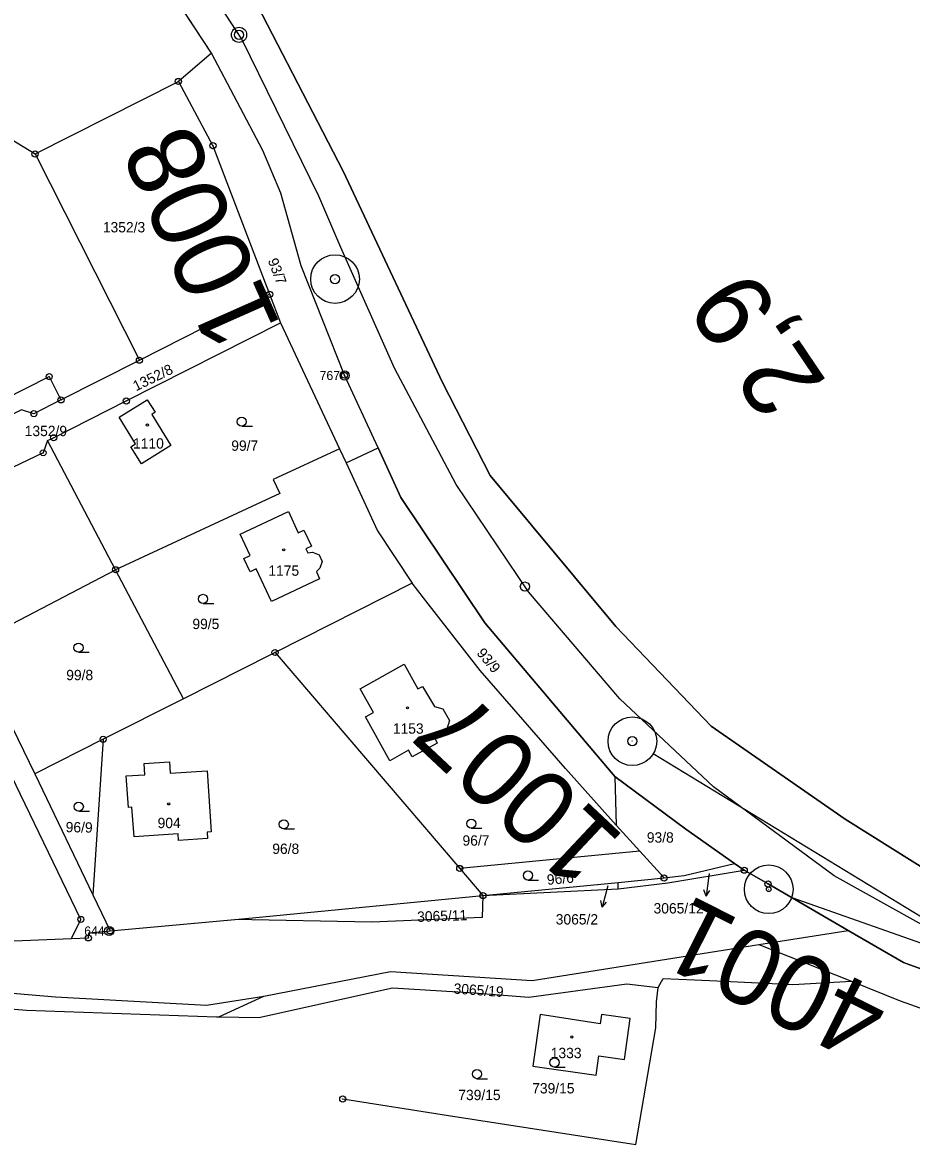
# Model space of a CAD drawing. Extents: x -728802 to -728097, y -1073200 to -1072700.
# Drawn here: x -728717.3 to -728571.2, y -1073057.7 to -1072873.2 of the extents above; entities that cross this region are included whole.
import ezdxf

# ---------------------------------------------------------------- set-up
doc = ezdxf.new("R2010")
doc.units = 0
for name, color, linetype in [('A5_JŽM', 7, 'Continuous'), ('body_ZBP', 7, 'Continuous'), ('body_ZBP-zničený', 7, 'Continuous'), ('body_ZBP_nový', 7, 'Continuous'), ('Hranice parcel', 7, 'Continuous'), ('Pop  PČ popisy', 7, 'Continuous')]:
    doc.layers.add(name, color=color, linetype=linetype)

msp = doc.modelspace()

# ---------------------------------------------------------------- linework, layer by layer
at = {"layer": 'A5_JŽM'}
msp.add_line((-728664.46, -1072931.23), (-728664.36, -1072931.23), dxfattribs=at)
for points in [[(-728320.8, -1073026.91), (-728374.01, -1073033.72), (-728429.1, -1073040.75), (-728461.93, -1073044.27), (-728481.2, -1073044.81), (-728499.35, -1073043.65), (-728506.01, -1073042.74), (-728514.57, -1073041.33), (-728535.85, -1073036), (-728561.35, -1073026.11), (-728583.96, -1073013.52), (-728603.76, -1072998.89), (-728619.19, -1072984.42), (-728634.19, -1072966.82), (-728646.08, -1072949.19), (-728656.18, -1072930.07), (-728664.99, -1072910.23), (-728668.63, -1072901.81), (-728681.25, -1072876.02), (-728691.89, -1072859.66)], [(-728541.12, -1073039.22), (-728572.55, -1073027.78), (-728581.66, -1073022.5), (-728594.83, -1073014.86), (-728598.74, -1073012.6), (-728600.31, -1073011.5), (-728608.33, -1073005.87), (-728620.02, -1072997.18), (-728641.33, -1072971.93), (-728655.13, -1072951.34), (-728658.89, -1072943.19), (-728664.41, -1072931.23), (-728671.52, -1072913.23), (-728674.84, -1072901.32), (-728677.82, -1072894.3), (-728686.27, -1072878.28), (-728697.93, -1072860.51)], [(-728681.24, -1072865.51), (-728664.64, -1072897.67), (-728648.31, -1072932.44), (-728640.48, -1072947.72), (-728619.81, -1072972.56), (-728604.14, -1072988.92), (-728582.13, -1073004.22), (-728556.03, -1073020.59)]]:
    msp.add_lwpolyline(points, dxfattribs=at)
for centre, radius in [((-728681.73, -1072875.28), 1.25), ((-728681.73, -1072875.28), 0.752), ((-728664.41, -1072931.23), 0.499), ((-728634.77, -1072965.97), 0.75)]:
    msp.add_circle(centre, radius, dxfattribs=at)
at = {"layer": 'body_ZBP'}
for p, q in [((-728665.94, -1072915.49), (-728665.98, -1072915.4)), ((-728617.07, -1072991.42), (-728617.15, -1072991.35)), ((-728524.75, -1073047.65), (-728613.69, -1072993.47)), ((-728594.73, -1073015.73), (-728594.68, -1073015.74))]:
    msp.add_line(p, q, dxfattribs=at)
msp.add_lwpolyline([(-728590.94, -1073017.06), (-728505.86, -1073047.04)], dxfattribs=at)
for centre, radius in [((-728665.96, -1072915.44), 0.756), ((-728617.11, -1072991.39), 4), ((-728617.11, -1072991.39), 0.756), ((-728594.71, -1073015.73), 0.378)]:
    msp.add_circle(centre, radius, dxfattribs=at)
at = {"layer": 'body_ZBP-zničený'}
msp.add_circle((-728665.96, -1072915.44), 4, dxfattribs=at)
at = {"layer": 'body_ZBP_nový'}
msp.add_circle((-728594.71, -1073015.73), 4, dxfattribs=at)
at = {"layer": 'Hranice parcel'}
for p, q in [((-728686.27, -1072878.28), (-728697.93, -1072860.51)), ((-728686.27, -1072878.28), (-728691.7, -1072882.94)), ((-728740.25, -1072879.56), (-728715.25, -1072894.87)), ((-728715.25, -1072894.87), (-728691.7, -1072882.94)), ((-728715.25, -1072894.87), (-728698.09, -1072928.77)), ((-728698.09, -1072928.77), (-728676.7, -1072917.94)), ((-728676.7, -1072917.94), (-728674.91, -1072922.64)), ((-728674.91, -1072922.64), (-728665.22, -1072943.32)), ((-728710.98, -1072935.3), (-728698.09, -1072928.77)), ((-728681.29, -1072939.62), (-728679.54, -1072939.62)), ((-728702.01, -1072963.21), (-728713.2, -1072941.99)), ((-728665.22, -1072943.32), (-728664.14, -1072945.63)), ((-728664.14, -1072945.63), (-728658.89, -1072943.19)), ((-728725.65, -1072975.57), (-728702.01, -1072963.21)), ((-728690.84, -1072984.4), (-728702.01, -1072963.21)), ((-728653.3, -1072965.44), (-728675.82, -1072976.81)), ((-728651.42, -1072967.85), (-728653.3, -1072965.44)), ((-728687.64, -1072968.75), (-728685.89, -1072968.75)), ((-728707.72, -1073020.69), (-728728.75, -1072977.2)), ((-728708.11, -1072976.78), (-728706.36, -1072976.78)), ((-728675.82, -1072976.81), (-728645.47, -1073012.3)), ((-728690.84, -1072984.4), (-728704.05, -1072991.07)), ((-728704.05, -1072991.07), (-728715.29, -1072996.74)), ((-728704.05, -1072991.07), (-728705.76, -1073016.63)), ((-728715.29, -1072996.74), (-728705.76, -1073016.63)), ((-728620.02, -1072997.18), (-728619.75, -1073005.17)), ((-728708.06, -1073002.9), (-728706.31, -1073002.9)), ((-728674.38, -1073005.8), (-728672.63, -1073005.8)), ((-728643.57, -1073005.69), (-728641.82, -1073005.69)), ((-728615.86, -1073009.48), (-728619.75, -1073005.17)), ((-728615.86, -1073009.48), (-728645.47, -1073012.3)), ((-728611.9, -1073013.87), (-728615.86, -1073009.48)), ((-728645.47, -1073012.3), (-728641.66, -1073016.76)), ((-728600.31, -1073011.5), (-728598.74, -1073012.6)), ((-728598.74, -1073012.6), (-728594.83, -1073014.86)), ((-728641.66, -1073016.76), (-728619.47, -1073014.61)), ((-728634.26, -1073014.22), (-728632.51, -1073014.22)), ((-728619.47, -1073014.61), (-728611.9, -1073013.87)), ((-728619.45, -1073015.63), (-728619.47, -1073014.61)), ((-728594.83, -1073014.86), (-728581.66, -1073022.5)), ((-728705.76, -1073016.63), (-728702.91, -1073022.58)), ((-728641.66, -1073016.76), (-728619.45, -1073015.63)), ((-728709.27, -1073023.84), (-728707.72, -1073020.69)), ((-728702.91, -1073022.58), (-728682.44, -1073020.7)), ((-728726.2, -1073024.5), (-728709.27, -1073023.84)), ((-728596.32, -1073024.82), (-728581.66, -1073022.5)), ((-728596.32, -1073024.82), (-728581.13, -1073030.83)), ((-728685.04, -1073036.71), (-728677.64, -1073033.29)), ((-728613.14, -1073034.24), (-728612.89, -1073031.9)), ((-728629.9, -1073044.95), (-728628.15, -1073044.95)), ((-728642.65, -1073046.86), (-728640.9, -1073046.86)), ((-728664.69, -1073050.2), (-728647.33, -1073052.89)), ((-728647.33, -1073052.89), (-728616.56, -1073057.69))]:
    msp.add_line(p, q, dxfattribs=at)
for points in [[(-728509.9, -1073046.86), (-728508.93, -1073042.5), (-728513.22, -1073039.89), (-728513.66, -1073035.13), (-728514.64, -1073029.26), (-728515.01, -1073025.35), (-728515.38, -1073021.39), (-728541.24, -1073024.99), (-728556.03, -1073020.59), (-728582.13, -1073004.22), (-728604.14, -1072988.92), (-728619.81, -1072972.56), (-728640.48, -1072947.72), (-728648.31, -1072932.44), (-728664.64, -1072897.67), (-728681.24, -1072865.51), (-728697.08, -1072846.24), (-728715.84, -1072827.08), (-728724.75, -1072819.77), (-728735.02, -1072812.66), (-728738.25, -1072810.52), (-728762.66, -1072797.6), (-728789.42, -1072788.62), (-728800, -1072785.75)], [(-728658.89, -1072943.19), (-728664.41, -1072931.23), (-728671.52, -1072913.23), (-728674.84, -1072901.32), (-728677.82, -1072894.3), (-728686.27, -1072878.28)], [(-728691.7, -1072882.94), (-728686.01, -1072893.51), (-728676.7, -1072917.94)], [(-728713.2, -1072941.99), (-728712.19, -1072941.51), (-728700.25, -1072935.47), (-728674.91, -1072922.64)], [(-728742.89, -1072957.06), (-728742.61, -1072946.49), (-728720.35, -1072935.22), (-728712.92, -1072931.46), (-728710.98, -1072935.3)], [(-728710.98, -1072935.3), (-728715.44, -1072937.56), (-728717.46, -1072936.9), (-728720.53, -1072938.46)], [(-728699.51, -1072943.01), (-728698.75, -1072942.53), (-728701.45, -1072938.15), (-728696.81, -1072935.29), (-728695.52, -1072937.32), (-728696.05, -1072937.71), (-728692.92, -1072942.8), (-728697.78, -1072945.82), (-728699.51, -1072943.01)], [(-728713.2, -1072941.99), (-728713.91, -1072943.99), (-728718.94, -1072946.39)], [(-728665.22, -1072943.32), (-728676.11, -1072948.38), (-728675.03, -1072950.69), (-728702.01, -1072963.21)], [(-728658.89, -1072943.19), (-728655.13, -1072951.34), (-728641.33, -1072971.93), (-728620.02, -1072997.18)], [(-728664.14, -1072945.63), (-728658.98, -1072956.84), (-728653.3, -1072965.44)], [(-728679.92, -1072960.89), (-728681.56, -1072957.34), (-728673.63, -1072953.66), (-728671.99, -1072957.16), (-728671.07, -1072956.72), (-728669.83, -1072959.34), (-728670.78, -1072959.75), (-728670.44, -1072960.42), (-728669.64, -1072960.34), (-728668.55, -1072960.74), (-728668.06, -1072961.84), (-728668.47, -1072962.95), (-728669.01, -1072963.48), (-728668.94, -1072963.65), (-728668.49, -1072964.73), (-728676.42, -1072968.43), (-728678.91, -1072963.06), (-728679.91, -1072963.53), (-728680.92, -1072961.35), (-728679.92, -1072960.89)], [(-728619.75, -1073005.17), (-728628.12, -1072995.9), (-728642.12, -1072979.76), (-728651.42, -1072967.85)], [(-728725.65, -1072975.57), (-728722.83, -1072981.3), (-728715.29, -1072996.74)], [(-728675.82, -1072976.81), (-728676.45, -1072977.13), (-728690.84, -1072984.4)], [(-728649.64, -1072985.67), (-728648.26, -1072986.08), (-728647.18, -1072987.97), (-728647.58, -1072989.39), (-728647.91, -1072990.21), (-728648.9, -1072990.74), (-728649.27, -1072990.62), (-728649.61, -1072990.81), (-728649.16, -1072991.69), (-728653.29, -1072993.97), (-728653.91, -1072992.88), (-728656.95, -1072994.61), (-728660.97, -1072987.38), (-728659.66, -1072986.65), (-728661.82, -1072982.76), (-728654.58, -1072978.73), (-728652.33, -1072982.79), (-728651.61, -1072982.39), (-728649.64, -1072985.67)], [(-728699.33, -1073002.26), (-728699.87, -1073002.3), (-728700.26, -1072997.11), (-728697.19, -1072996.91), (-728697.31, -1072995.08), (-728693.16, -1072994.76), (-728693.04, -1072996.64), (-728686.96, -1072996.24), (-728686.3, -1073006.28), (-728686.99, -1073006.32), (-728686.92, -1073007.41), (-728691.67, -1073007.72), (-728691.74, -1073006.63), (-728698.96, -1073007.1), (-728699.33, -1073002.26)], [(-728620.02, -1072997.18), (-728608.33, -1073005.87), (-728600.31, -1073011.5)], [(-728619.45, -1073015.63), (-728611.28, -1073014.65), (-728598.74, -1073012.6)], [(-728611.9, -1073013.87), (-728608.61, -1073013.46), (-728600.31, -1073011.5)], [(-728641.66, -1073016.76), (-728641.79, -1073020.38), (-728659.93, -1073021.15), (-728682.44, -1073020.7)], [(-728682.44, -1073020.7), (-728679.52, -1073020.43), (-728641.66, -1073016.76)], [(-728709.27, -1073023.84), (-728706.47, -1073023.73), (-728706.38, -1073022.87), (-728702.91, -1073022.58)], [(-728581.66, -1073022.5), (-728572.55, -1073027.78), (-728541.12, -1073039.22)], [(-728677.64, -1073033.29), (-728656.86, -1073029.26), (-728633.57, -1073030.7), (-728596.32, -1073024.82)], [(-728685.04, -1073036.71), (-728678.46, -1073036.79), (-728656.52, -1073031.93), (-728643.1, -1073032.77), (-728634.11, -1073033.48), (-728618.03, -1073031.25), (-728612.89, -1073031.9), (-728612.03, -1073030.4), (-728606.88, -1073030.63), (-728603.24, -1073030.8), (-728590.77, -1073031.36), (-728581.13, -1073030.83)], [(-728581.13, -1073030.83), (-728573.14, -1073034.08), (-728549.07, -1073042.59), (-728532.43, -1073048.47), (-728518.44, -1073050.34), (-728510.92, -1073051.33), (-728509.9, -1073046.86)], [(-728800, -1073042), (-728754.78, -1073034.24), (-728729.22, -1073031.95), (-728711.87, -1073033.42), (-728687.08, -1073034.79), (-728677.64, -1073033.29)], [(-728800, -1073046.03), (-728776.74, -1073043.15), (-728750.7, -1073037.52), (-728729.9, -1073034.48), (-728716.63, -1073035.6), (-728685.42, -1073036.71), (-728685.04, -1073036.71)], [(-728616.56, -1073057.69), (-728613.27, -1073038.52), (-728613.14, -1073034.24)], [(-728633.49, -1073044.79), (-728623.08, -1073046.28), (-728622.63, -1073043.11), (-728618.43, -1073043.72), (-728617.47, -1073036.95), (-728622.19, -1073036.29), (-728622.39, -1073037.83), (-728632.28, -1073036.32), (-728633.49, -1073044.79)]]:
    msp.add_lwpolyline(points, dxfattribs=at)
for centre, radius in [((-728691.7, -1072882.94), 0.5), ((-728691.7, -1072882.94), 0.0303), ((-728686.01, -1072893.51), 0.5), ((-728715.25, -1072894.87), 0.5), ((-728715.25, -1072894.87), 0.0303), ((-728686.01, -1072893.51), 0.0303), ((-728676.7, -1072917.94), 0.5), ((-728676.7, -1072917.94), 0.0303), ((-728698.09, -1072928.77), 0.5), ((-728698.09, -1072928.77), 0.0303), ((-728712.92, -1072931.46), 0.5), ((-728712.92, -1072931.46), 0.0303), ((-728664.39, -1072931.28), 0.75), ((-728664.41, -1072931.23), 0.5), ((-728664.41, -1072931.23), 0.0303), ((-728664.39, -1072931.28), 0.03), ((-728710.98, -1072935.3), 0.5), ((-728710.98, -1072935.3), 0.0303), ((-728700.25, -1072935.47), 0.5), ((-728700.25, -1072935.47), 0.0303), ((-728715.44, -1072937.56), 0.5), ((-728715.44, -1072937.56), 0.0303), ((-728696.79, -1072939.42), 0.175), ((-728681.29, -1072938.87), 0.75), ((-728712.19, -1072941.51), 0.5), ((-728712.19, -1072941.51), 0.0303), ((-728713.91, -1072943.99), 0.5), ((-728713.91, -1072943.99), 0.0303), ((-728674.39, -1072959.93), 0.175), ((-728702.01, -1072963.21), 0.5), ((-728702.01, -1072963.21), 0.0303), ((-728687.64, -1072968), 0.75), ((-728708.11, -1072976.03), 0.75), ((-728675.82, -1072976.81), 0.5), ((-728675.82, -1072976.81), 0.0303), ((-728654.05, -1072985.9), 0.175), ((-728704.05, -1072991.07), 0.5), ((-728704.05, -1072991.07), 0.0303), ((-728708.06, -1073002.15), 0.75), ((-728693.29, -1073001.7), 0.175), ((-728674.38, -1073005.05), 0.75), ((-728643.57, -1073004.94), 0.75), ((-728645.47, -1073012.3), 0.5), ((-728645.47, -1073012.3), 0.0303), ((-728634.26, -1073013.47), 0.75), ((-728598.74, -1073012.6), 0.5), ((-728598.74, -1073012.6), 0.0303), ((-728611.9, -1073013.87), 0.5), ((-728611.9, -1073013.87), 0.0303), ((-728594.83, -1073014.86), 0.5), ((-728594.83, -1073014.86), 0.0303), ((-728641.66, -1073016.76), 0.5), ((-728641.66, -1073016.76), 0.0303), ((-728707.72, -1073020.69), 0.5), ((-728707.72, -1073020.69), 0.0303), ((-728703.06, -1073022.59), 0.75), ((-728702.91, -1073022.58), 0.5), ((-728706.47, -1073023.73), 0.5), ((-728706.47, -1073023.73), 0.0303), ((-728703.06, -1073022.59), 0.03), ((-728702.91, -1073022.58), 0.0303), ((-728627.06, -1073040.01), 0.175), ((-728629.9, -1073044.2), 0.75), ((-728642.65, -1073046.11), 0.75), ((-728664.69, -1073050.2), 0.5), ((-728664.69, -1073050.2), 0.0303)]:
    msp.add_circle(centre, radius, dxfattribs=at)
at = {"layer": 'Pop  PČ popisy'}
for p, q in [((-728604.52, -1073013.11), (-728604.61, -1073013.9)), ((-728604.61, -1073013.9), (-728604.98, -1073016.88)), ((-728621.32, -1073015.79), (-728622.1, -1073018.69)), ((-728621.15, -1073015.17), (-728621.32, -1073015.79)), ((-728604.98, -1073016.88), (-728605.35, -1073015.82)), ((-728604.98, -1073016.88), (-728604.36, -1073015.95)), ((-728622.1, -1073018.69), (-728622.32, -1073017.59)), ((-728622.1, -1073018.69), (-728621.35, -1073017.85))]:
    msp.add_line(p, q, dxfattribs=at)

# ---------------------------------------------------------------- texts
at = {"layer": 'A5_JŽM'}
msp.add_text('2,9', height=12.5, rotation=123.9838, dxfattribs=at).set_placement((-728585.02, -1072932.44))
at = {"layer": 'body_ZBP'}
msp.add_text('1007', height=12.5, rotation=136.8293, dxfattribs=at).set_placement((-728618.12, -1073007.35))
at = {"layer": 'body_ZBP-zničený'}
msp.add_text('1008', height=12.5, rotation=113.9263, dxfattribs=at).set_placement((-728674.76, -1072923.22))
at = {"layer": 'body_ZBP_nový'}
msp.add_text('4001', height=12.5, rotation=153.2359, dxfattribs=at).set_placement((-728574.2, -1073033.45))
at = {"layer": 'Hranice parcel'}
for s, height, p in [('1352/3', 1.7, (-728704.1, -1072907.76)), ('767', 1.5, (-728668.49, -1072932.03)), ('1352/9', 1.7, (-728716.94, -1072941.25)), ('1110', 1.7, (-728699.14, -1072943.3)), ('99/7', 1.7, (-728683.01, -1072943.66)), ('1175', 1.7, (-728676.91, -1072964.2)), ('99/5', 1.7, (-728689.39, -1072972.96)), ('99/8', 1.7, (-728710.12, -1072981.36)), ('1153', 1.7, (-728656.46, -1072990.16)), ('904', 1.7, (-728695.11, -1073005.68)), ('96/7', 1.7, (-728645.02, -1073008.56)), ('93/8', 1.7, (-728614.74, -1073008.06)), ('96/8', 1.7, (-728676.27, -1073009.92)), ('3065/12', 1.7, (-728613.63, -1073019.71)), ('3065/2', 1.7, (-728629.7, -1073021.52)), ('644', 1.5, (-728707.16, -1073023.34)), ('1333', 1.7, (-728630.52, -1073043.49)), ('739/15', 1.7, (-728633.57, -1073049.29)), ('739/15', 1.7, (-728645.71, -1073050.39))]:
    msp.add_text(s, height=height, dxfattribs=at).set_placement(p)
for s, rotation, p in [('93/7', 291, (-728677.04, -1072912.38)), ('1352/8', 26, (-728698.65, -1072933.9)), ('93/9', 310, (-728642.8, -1072976.96)), ('96/9', 359, (-728710.22, -1073006.35)), ('96/6', 5, (-728631.08, -1073015.01)), ('3065/11', 2, (-728652.44, -1073021.1)), ('3065/19', 356, (-728646.53, -1073032.87))]:
    msp.add_text(s, height=1.7, rotation=rotation, dxfattribs=at).set_placement(p)

doc.saveas('drawing.dxf')
